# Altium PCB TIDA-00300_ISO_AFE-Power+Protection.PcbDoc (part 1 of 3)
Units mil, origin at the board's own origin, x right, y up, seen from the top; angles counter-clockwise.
Board outline 3622.05 x 2204.8 mil, 4 copper layers (Top Layer, GND Layer, PWR Layer, Bottom Layer), stack 63.6 mil thick; 240 components, 107 nets, 584 pads, 225 vias.
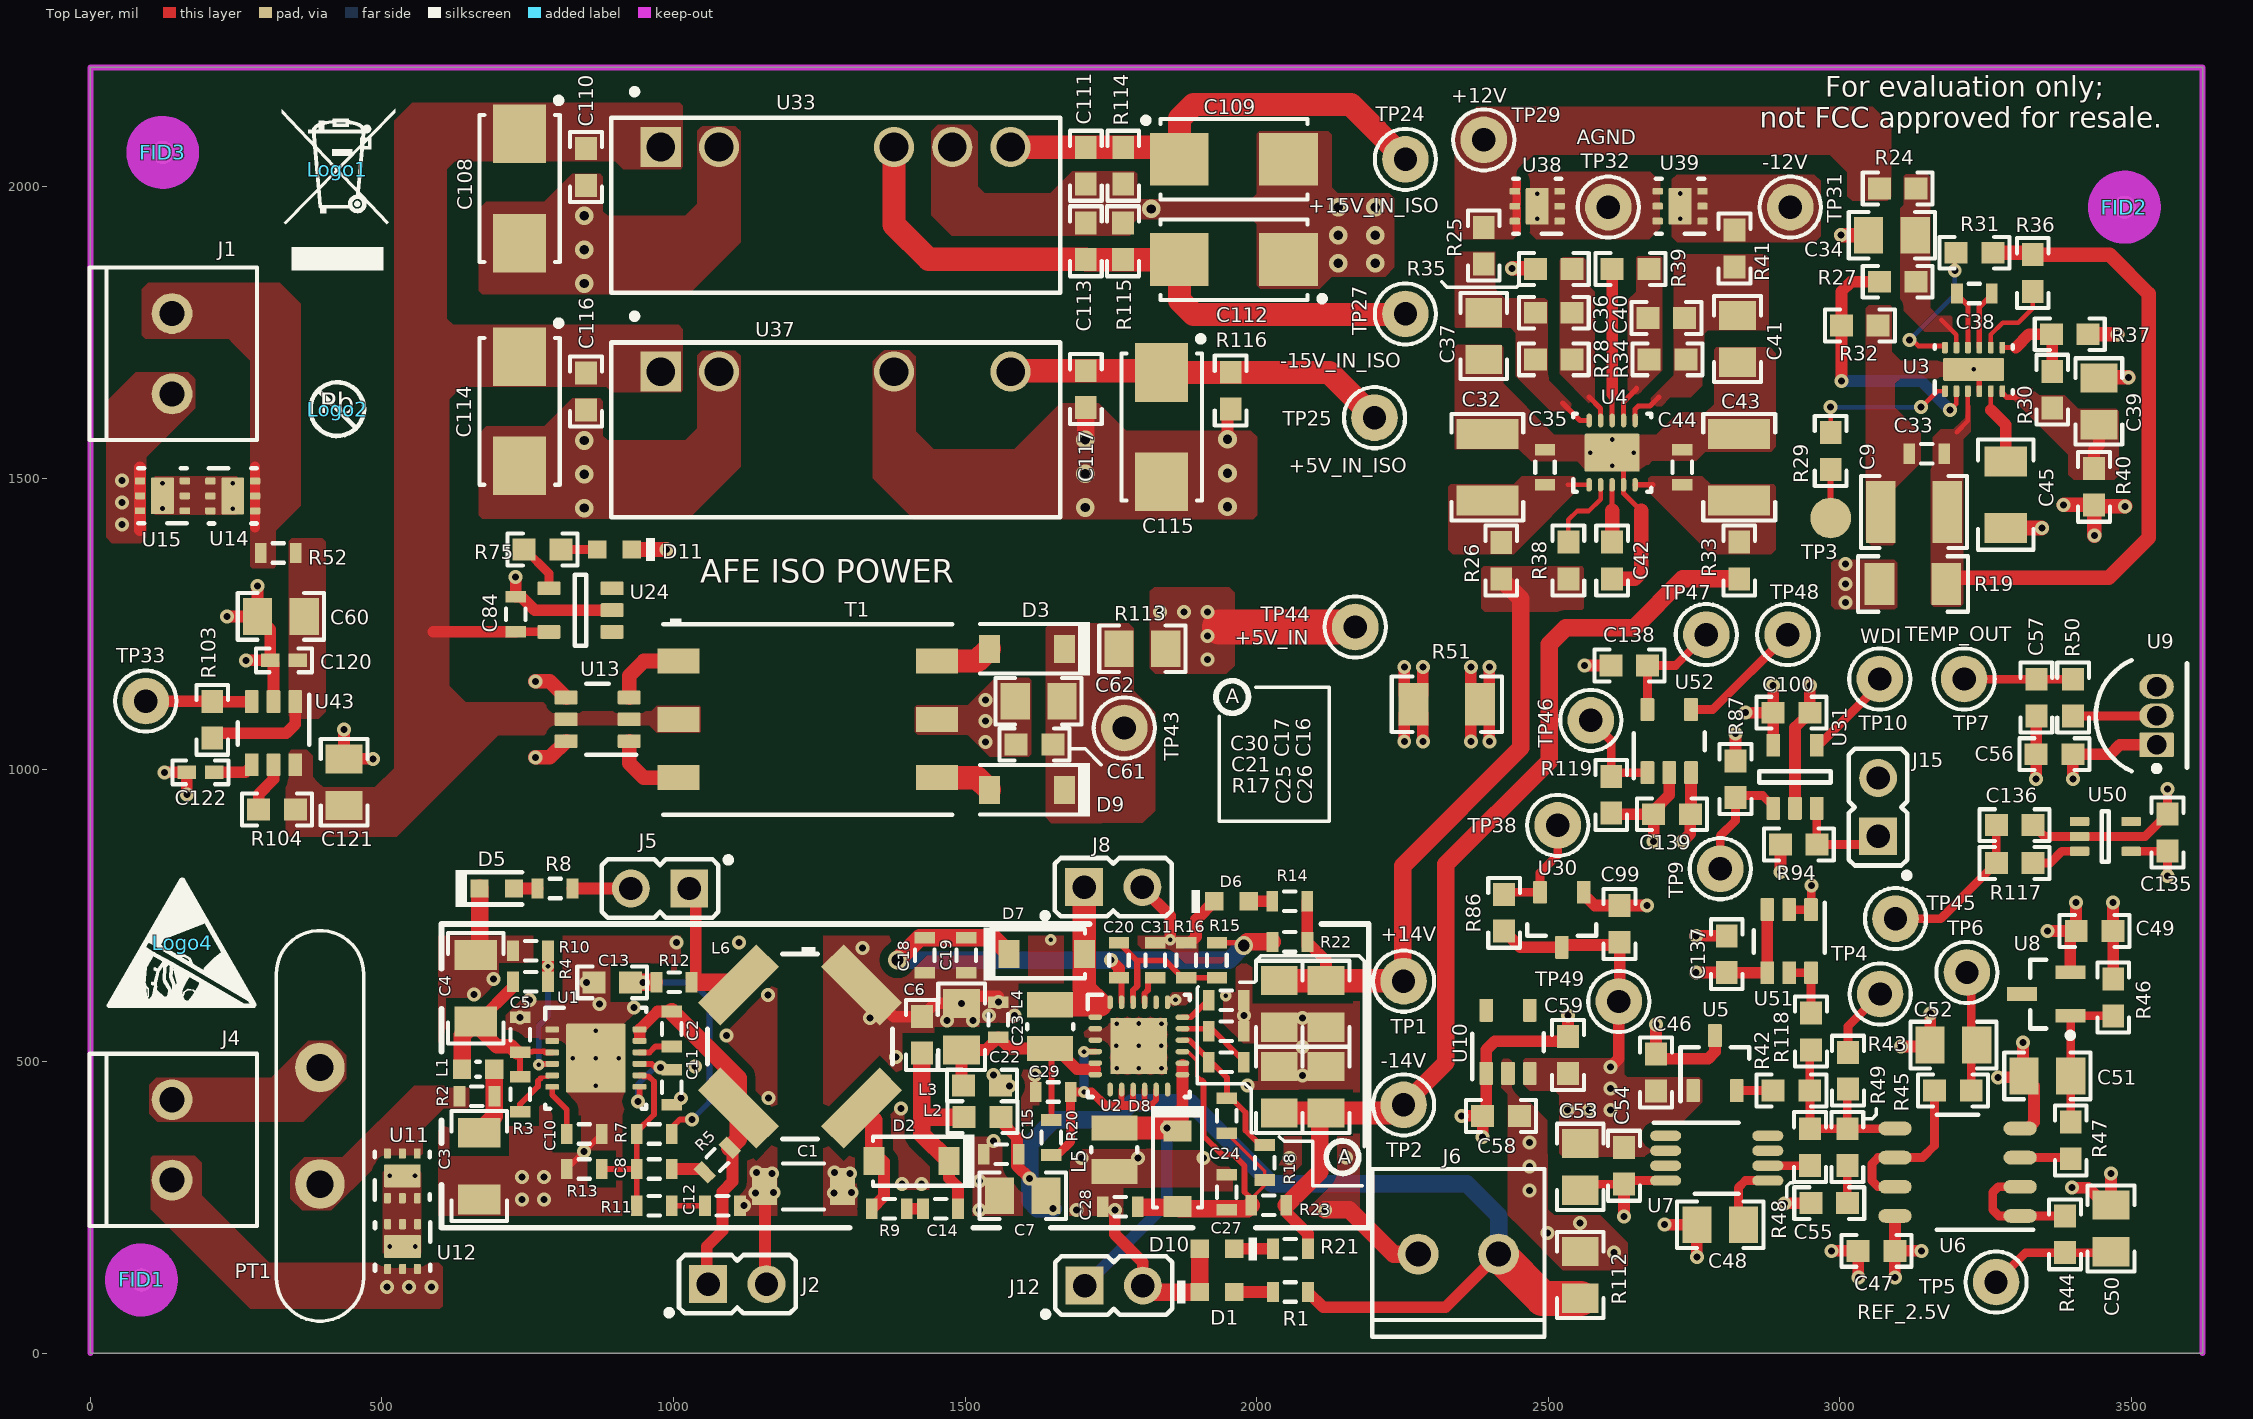
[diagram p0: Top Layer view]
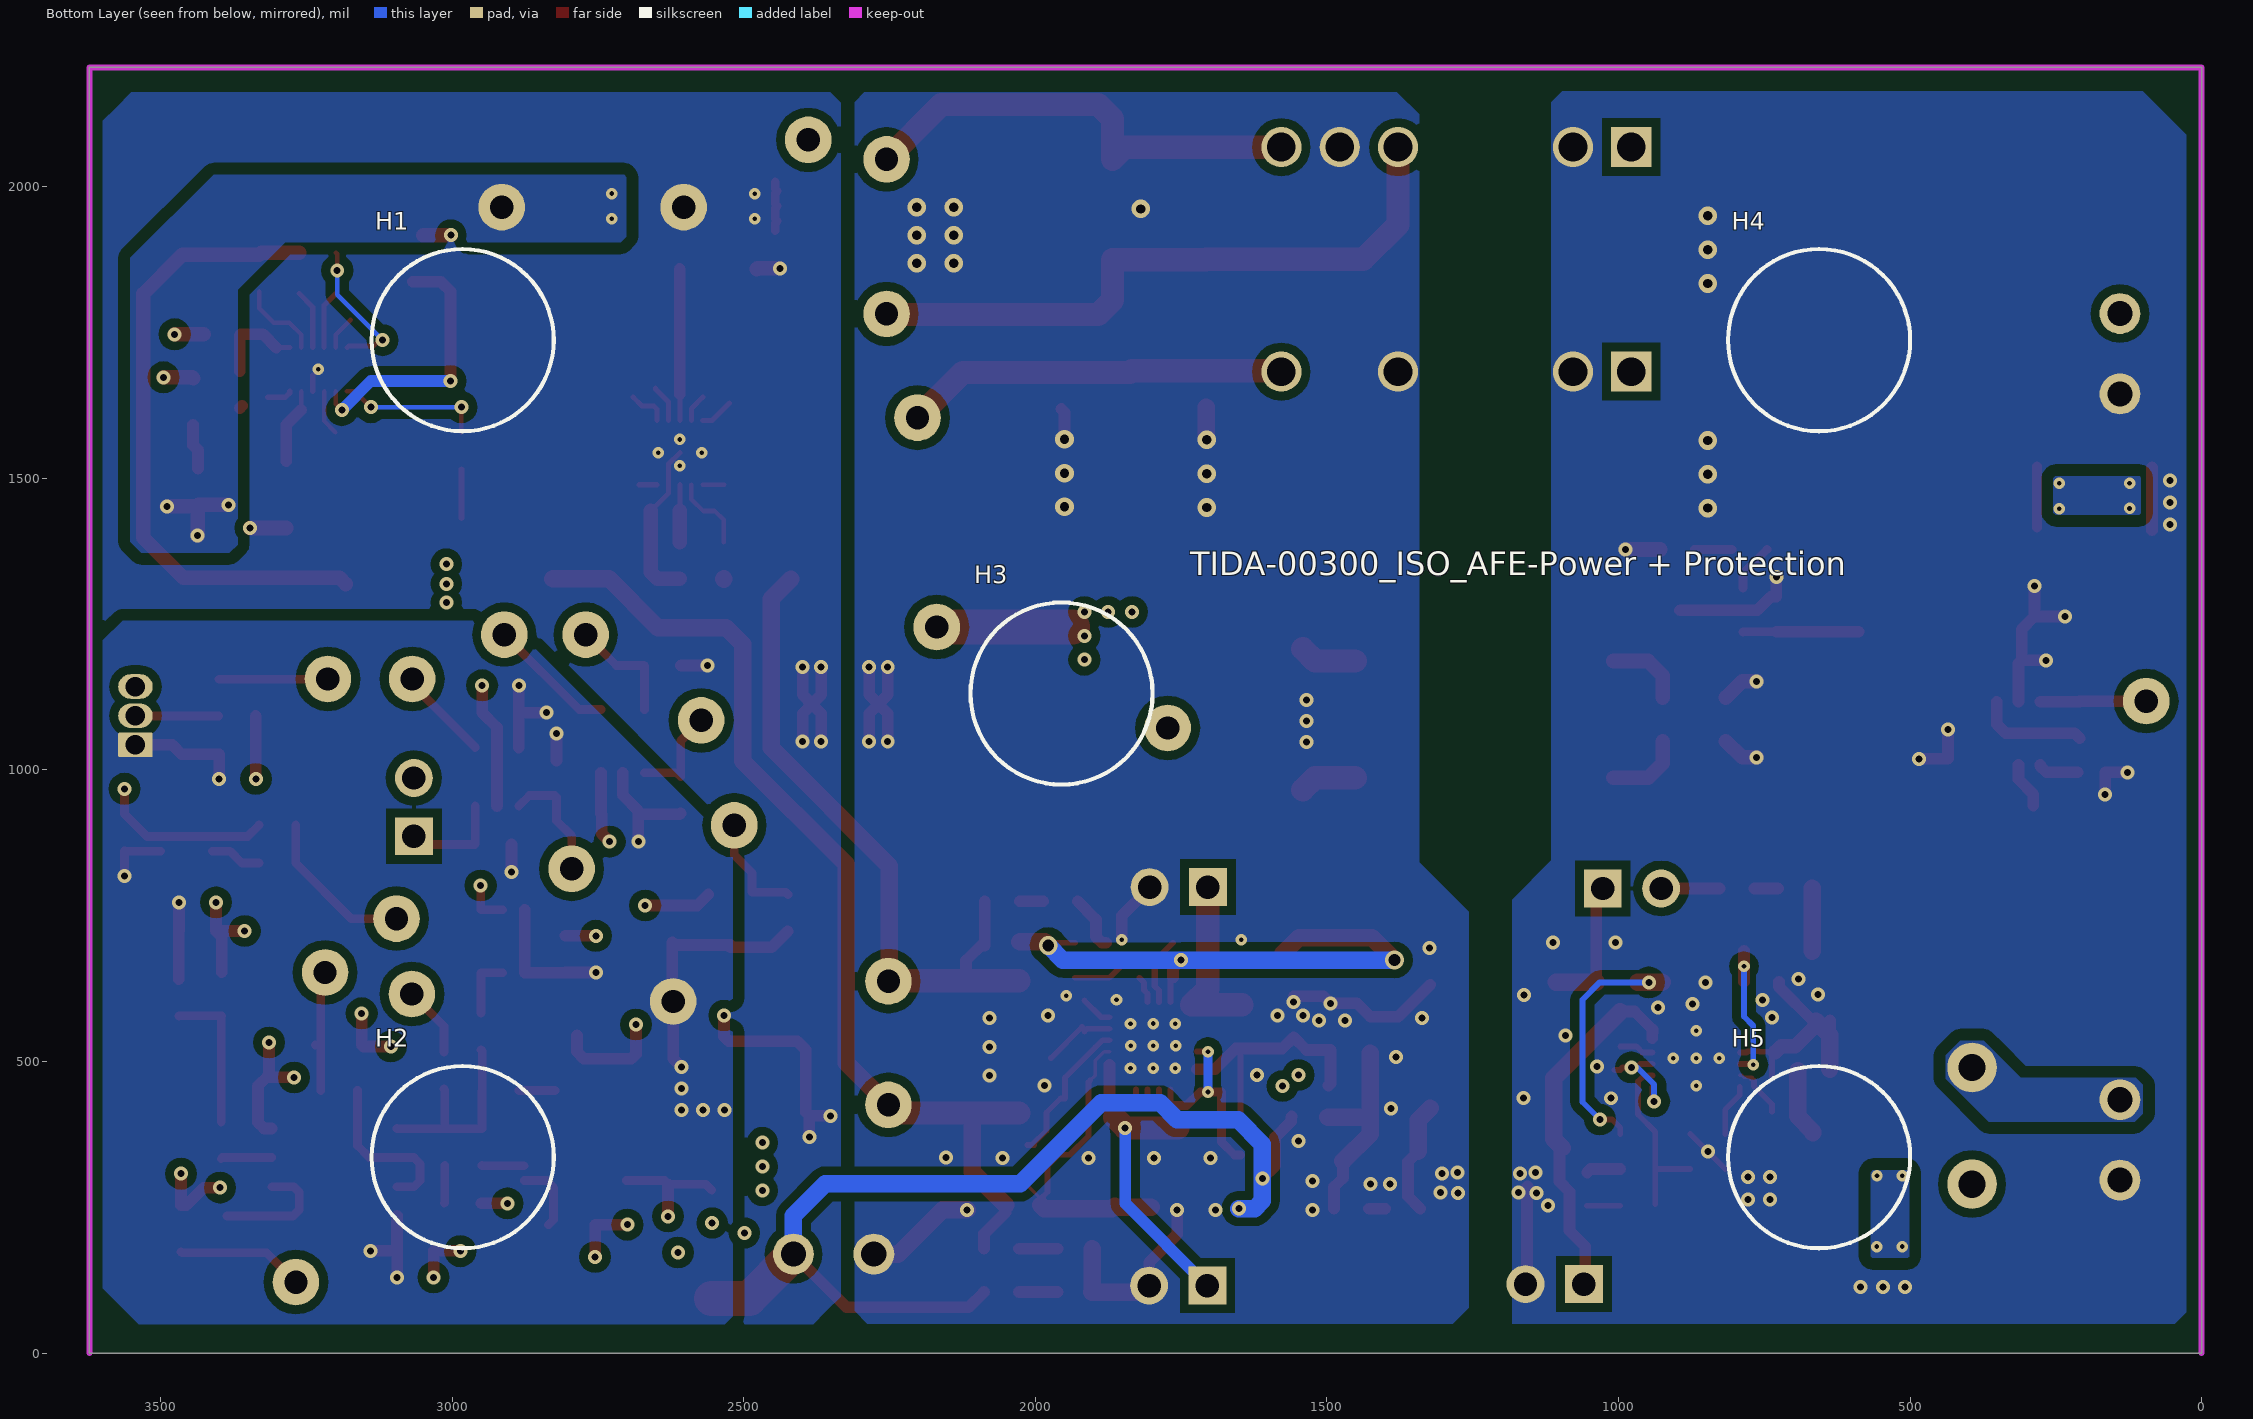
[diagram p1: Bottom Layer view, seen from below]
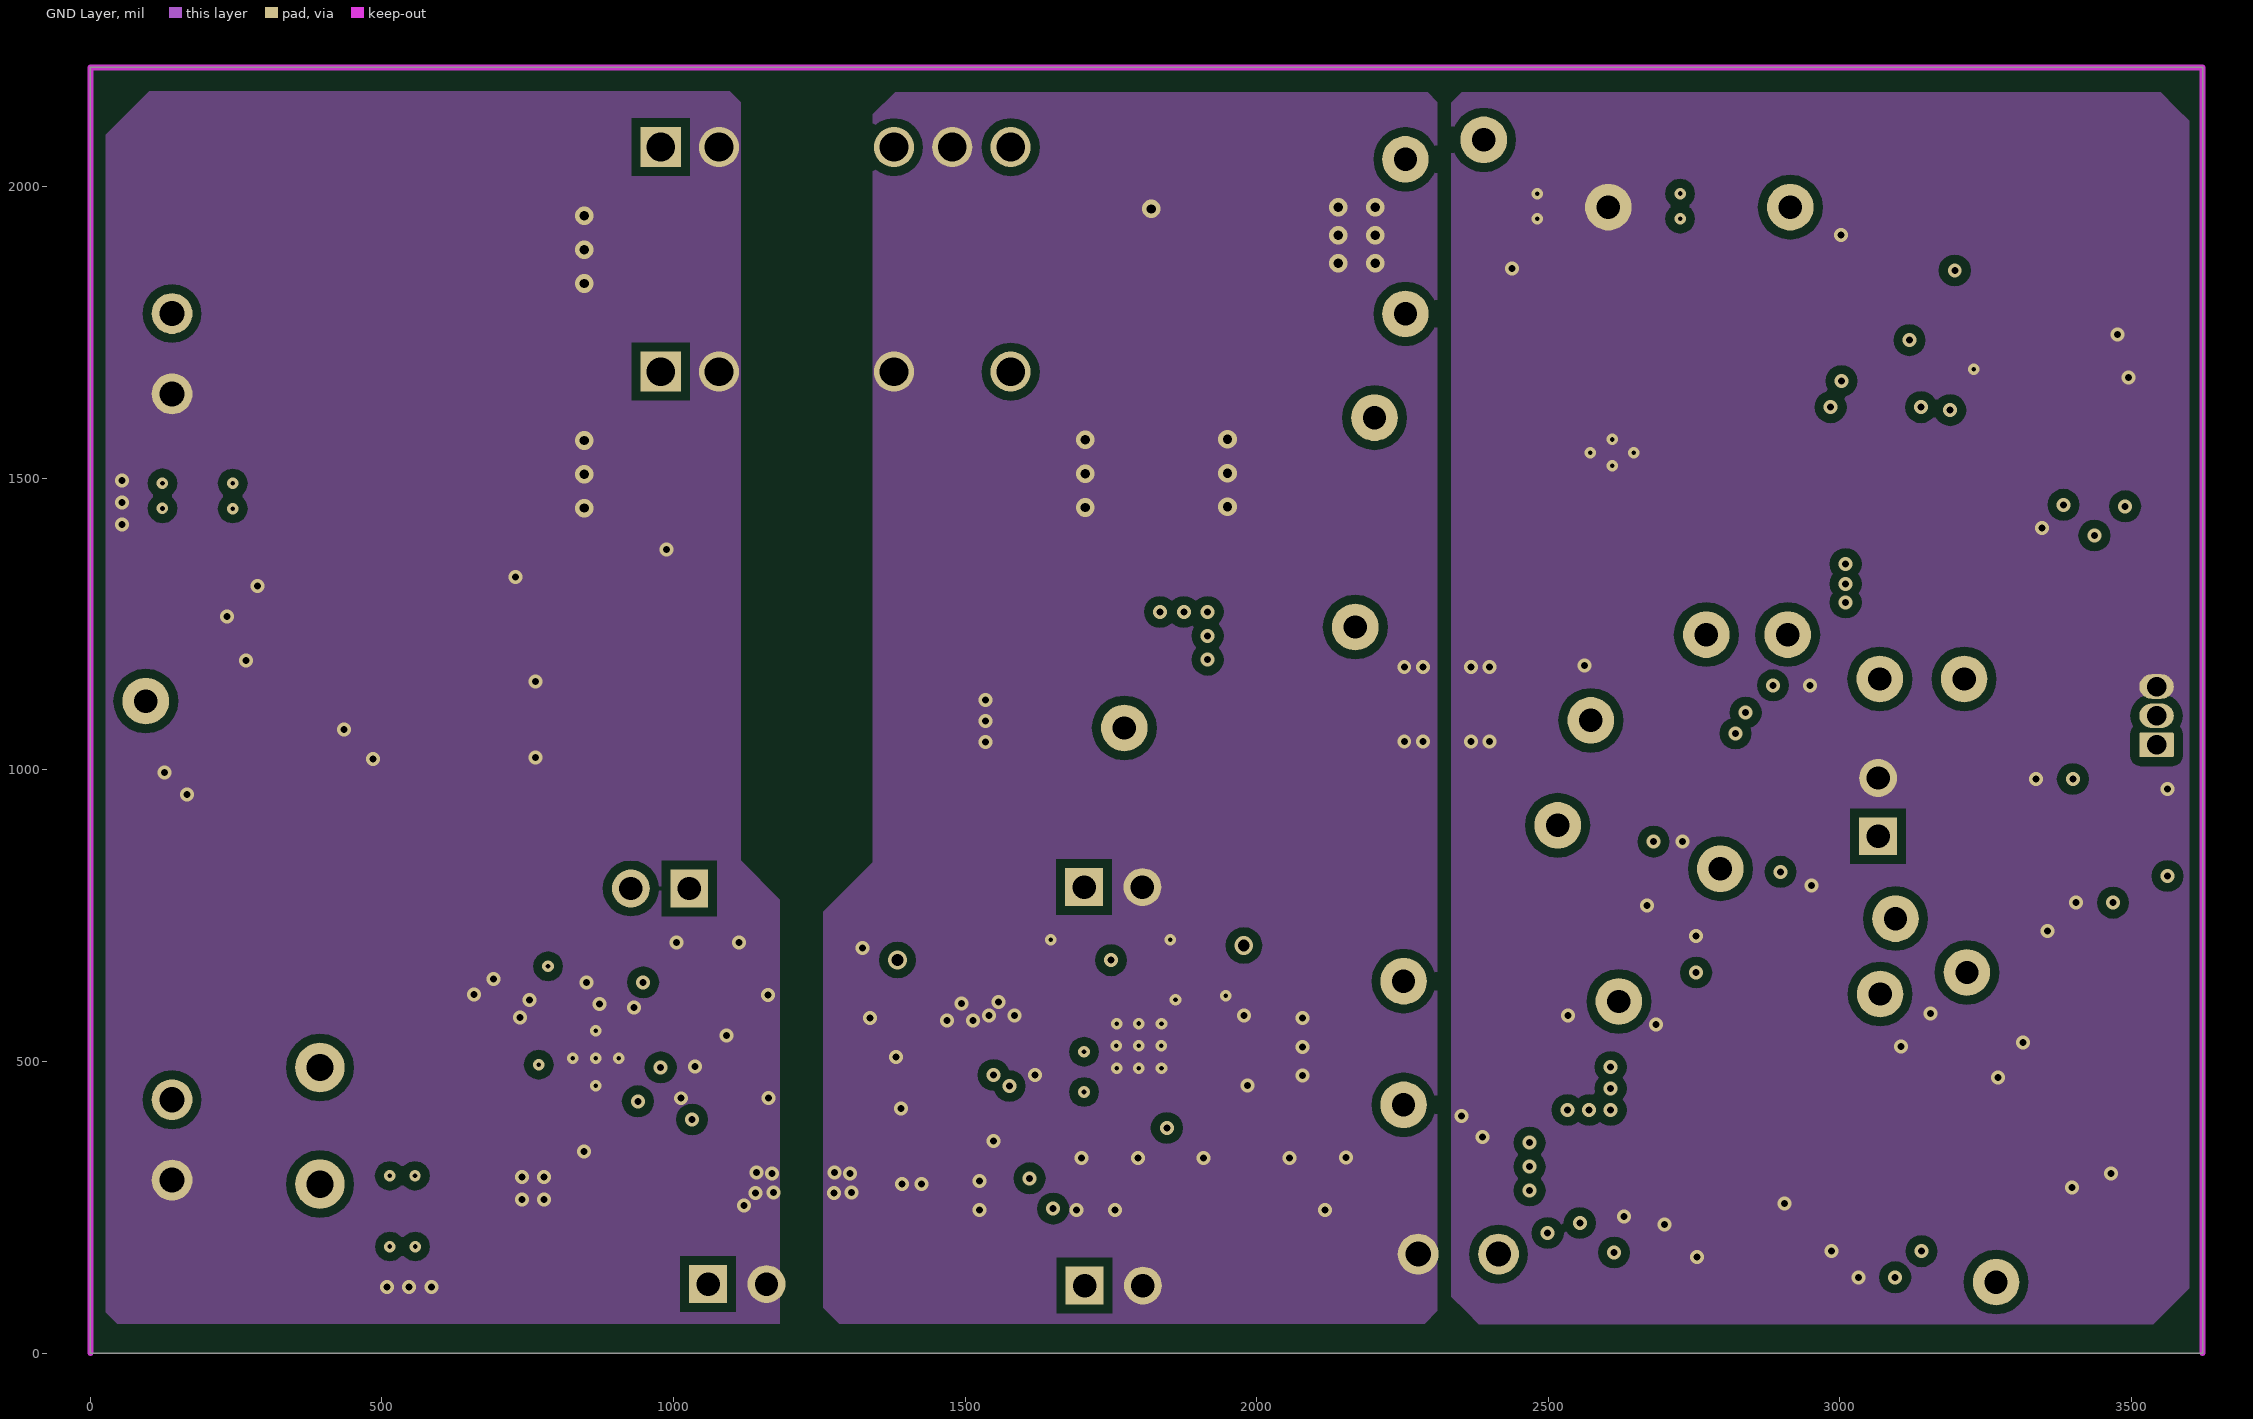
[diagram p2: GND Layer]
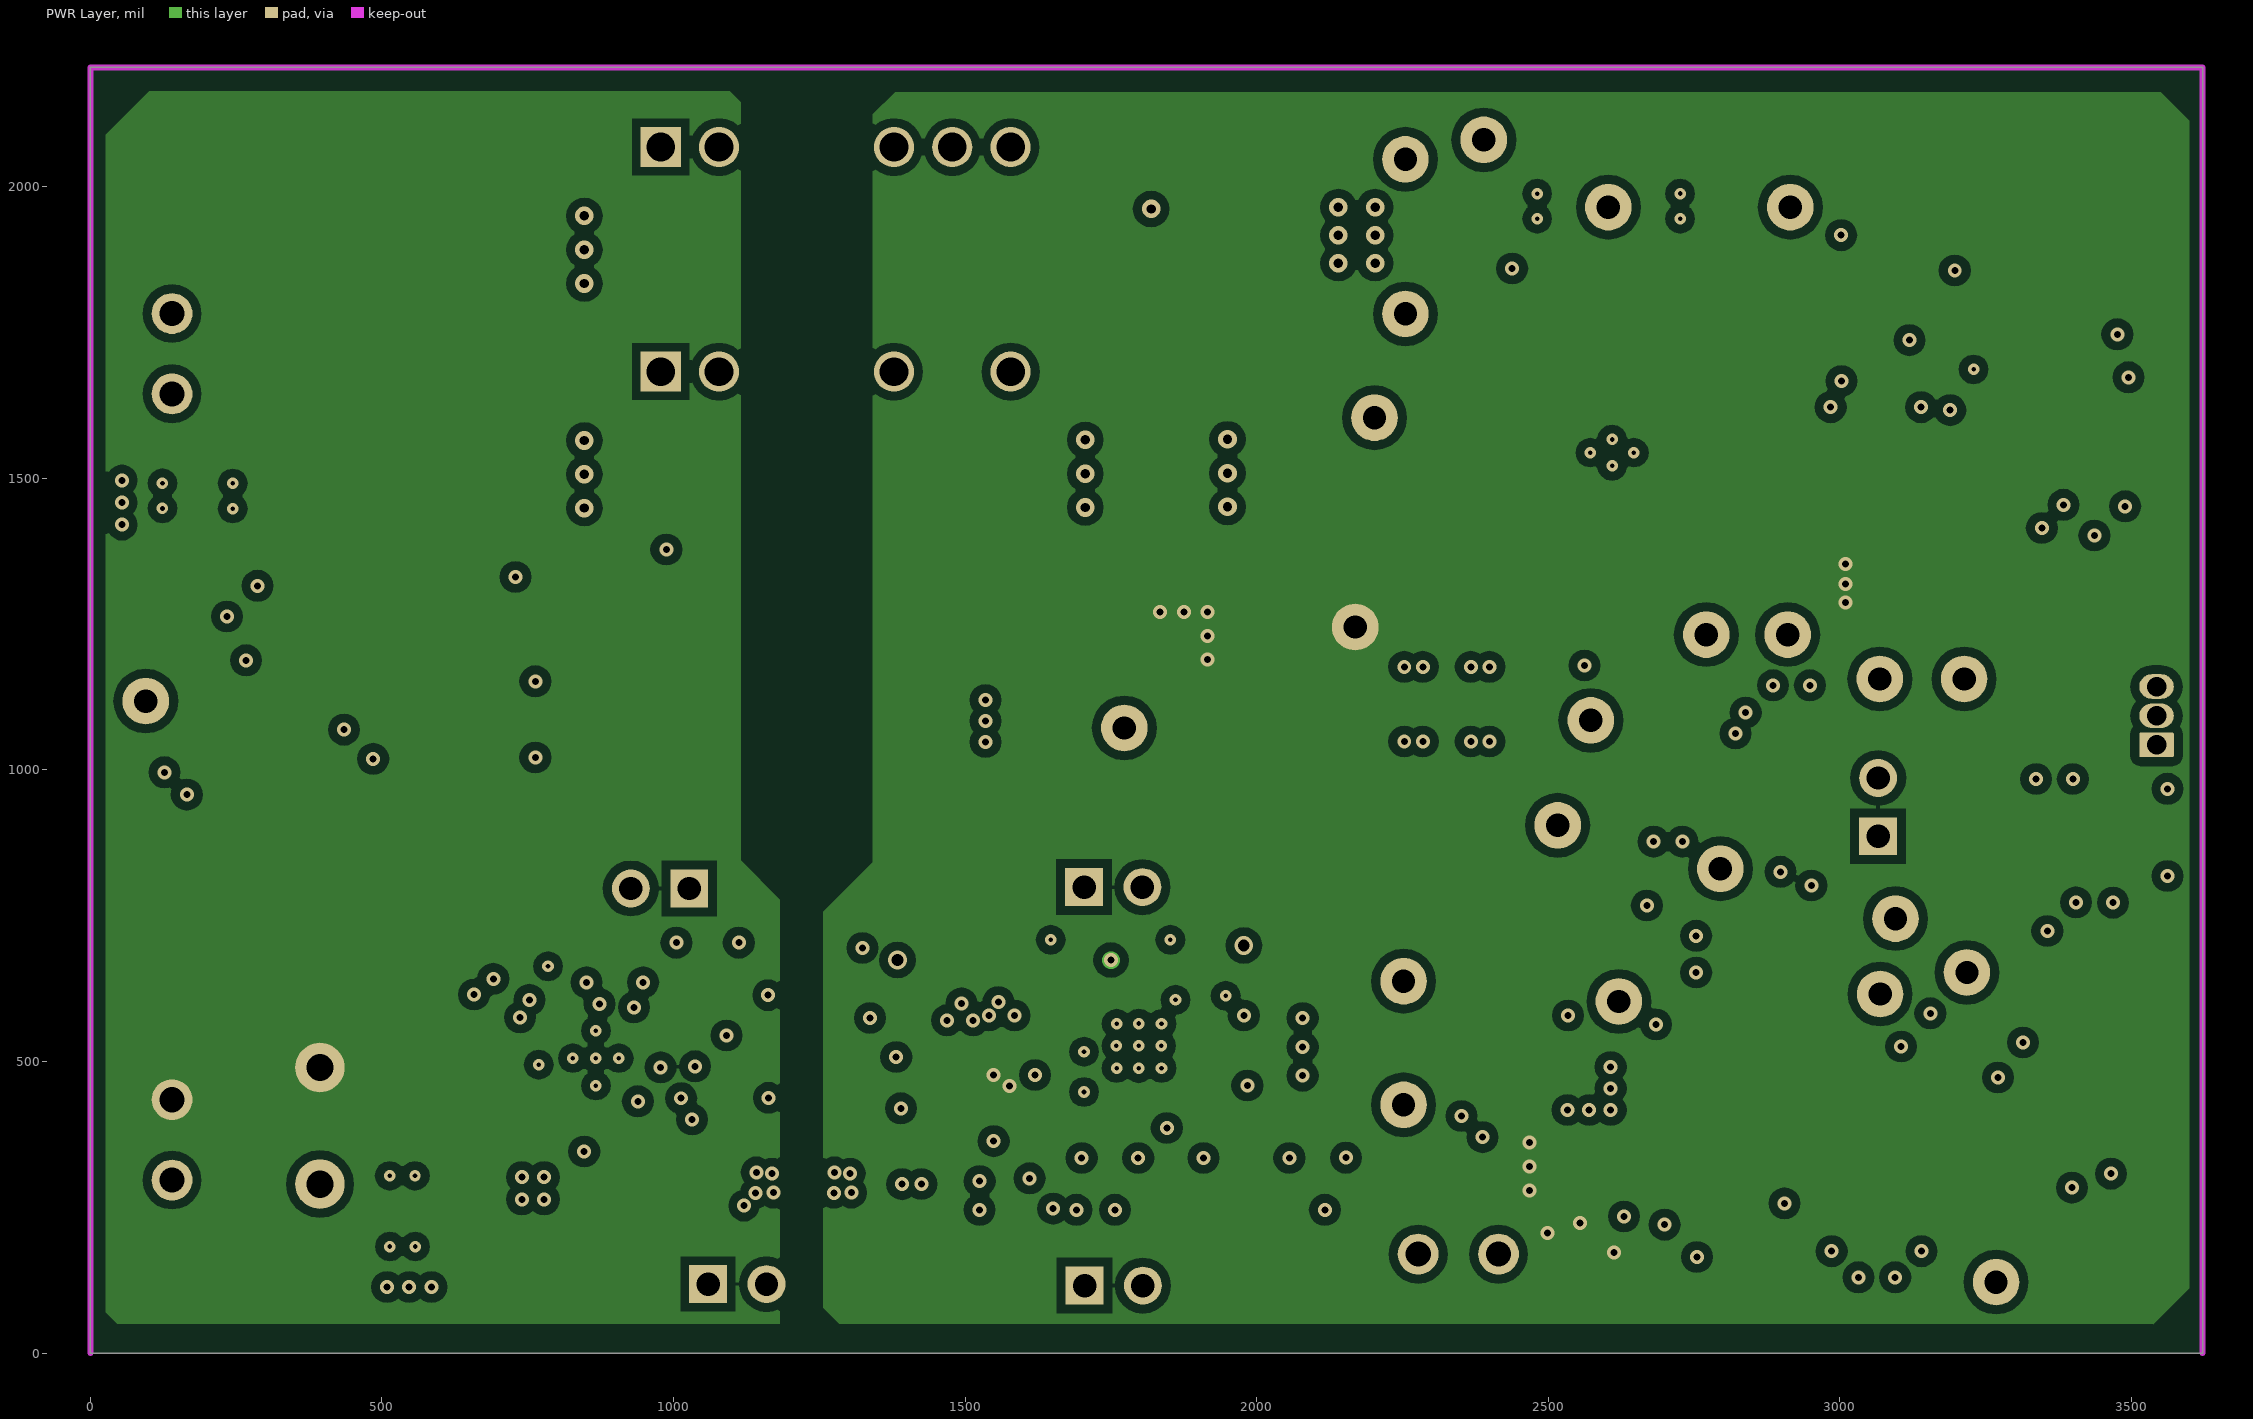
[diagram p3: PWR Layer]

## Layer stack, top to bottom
Top Solder: solder mask 0.3, Solder Resist, Dk 3.5
Top Layer: signal copper 1.4
Dielectric1: core 15, FR-4 High Tg, Dk 4.5
GND Layer: signal copper 1.4
Dielectric 2: prepreg 28, FR-4 High Tg, Dk 4.5
PWR Layer: signal copper 1.4
Dielectric 3: core 15, FR-4 High Tg, Dk 4.5
Bottom Layer: signal copper 1.4
Bottom Solder: solder mask 0.3, Solder Resist, Dk 3.5

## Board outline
0,0 0,2204.72 3622.05,2204.65 3622.05,-0.07

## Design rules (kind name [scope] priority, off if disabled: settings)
AcuteAngle [All] p1: minimum=4.50000000000000E+0001 checktracksonly=FALSE
AssemblyTestPointUsage [All] p1: valid=2
BoardOutlineClearance BoardOutlineClearance_MountingHoles [OnCopper and InComponentClass('Mounting Holes')] p1: gap=30 ignorepadtopadclearanceinfootprint=FALSE
BoardOutlineClearance BoardOutlineClearance_Poly [OnCopper and InPoly] p2: gap=25 ignorepadtopadclearanceinfootprint=FALSE
BoardOutlineClearance [OnCopper and Not InComponentClass('Logo') and not InComponentClass('FiducialMark') and not InRegion(1000,500,4000,800)] p3: gap=15 ignorepadtopadclearanceinfootprint=FALSE
Clearance Clearance_Poly_poly [InPoly vs InPoly] p1: gap=20 ignorepadtopadclearanceinfootprint=FALSE except(0: Arc-Hole Track-Hole SMDPad-Hole THPad-Hole Via-Hole Fill-Hole Poly-Hole Region-Hole Text-Hole)
Clearance Clearance_Keepouts [((IsTrack Or IsArc) And Not InPoly) And IsFree and IsKeepOut vs ((IsTrack Or IsArc) And Not InPoly) And IsFree and IsKeepOut] p2: gap=20 ignorepadtopadclearanceinfootprint=FALSE except(0: Arc-Hole Track-Hole SMDPad-Hole THPad-Hole Via-Hole Fill-Hole Poly-Hole Region-Hole Text-Hole)
Clearance Clearance_Poly [InPolygon] p3: gap=15 ignorepadtopadclearanceinfootprint=FALSE except(0: Arc-Hole Track-Hole SMDPad-Hole THPad-Hole Via-Hole Fill-Hole Poly-Hole Region-Hole Text-Hole)
Clearance [All] p4: gap=7.87 ignorepadtopadclearanceinfootprint=FALSE except(0: Arc-SMDPad Arc-THPad Arc-Hole Track-Hole SMDPad-Hole THPad-Hole Via-Hole Fill-Hole Poly-Hole Region-Hole Text-Hole)
ComponentClearance ComponentClearance_MountingHoles_FiducialMarks [InComponentClass('Mounting Holes') vs InComponentClass('FiducialMark')] p1: gap=10 collisioncheckmode=3 verticalgap=10 showdistances=FALSE
ComponentClearance ComponentClearance_Shunt [InComponentClass('Header') vs InComponentClass('Shunt')] p2: gap=0 collisioncheckmode=3 verticalgap=0 showdistances=FALSE
ComponentClearance ComponentClearance_Logo [InComponentClass('Logo')] p3: gap=5 collisioncheckmode=3 verticalgap=5 showdistances=FALSE
ComponentClearance ComponentClearance_ScrewToNut [(HasFootprint('NY PMS 440 0025 PH')) vs (HasFootprint('Keystone_1902C'))] p4: gap=5 collisioncheckmode=3 verticalgap=10 showdistances=FALSE
ComponentClearance ComponentClearance_MountingHoles [InComponentClass('Mounting Holes')] p5: gap=250 collisioncheckmode=3 verticalgap=100000 showdistances=FALSE
ComponentClearance ComponentClearance_SmallPassives [HasFootprint('0201*') or HasFootprint('0402*') or HasFootprint('0508') or HasFootprint('0603*') or HasFootprint('0612') or HasFootprint('0805*') or HasFootprint('0815*') or HasFootprint('0830*') or HasFootprint('1206*') or HasFootprint('1210*') or HasFootprint('1808*') or HasFootprint('1812*') or HasFootprint('1825*') or HasFootprint('2010*') or HasFootprint('2220*') or HasFootprint('2225*') or HasFootprint('2512*') or HasFootprint('2728*') or HasFootprint('3518*') vs HasFootprint('0201*') or HasFootprint('0402*') or HasFootprint('0508') or HasFootprint('0603*') or HasFootprint('0612') or HasFootprint('0805*') or HasFootprint('0815*') or HasFootprint('0830*') or HasFootprint('1206*') or HasFootprint('1210*') or HasFootprint('1808*') or HasFootprint('1812*') or HasFootprint('1825*') or HasFootprint('2010*') or HasFootprint('2220*') or HasFootprint('2225*') or HasFootprint('2512*') or HasFootprint('2728*') or HasFootprint('3518*')] p6: gap=5 collisioncheckmode=3 verticalgap=5 showdistances=FALSE
ComponentClearance ComponentClearance_THtoSMT [IsThruComponent vs IsSMTComponent] p7: gap=5 collisioncheckmode=3 verticalgap=5 showdistances=FALSE
ComponentClearance ComponentClearance_THtoTH [IsThruComponent vs IsThruComponent] p8: gap=0 collisioncheckmode=3 verticalgap=10 showdistances=FALSE
ComponentClearance [All] p9: gap=10 collisioncheckmode=3 verticalgap=10 showdistances=FALSE
DiffPairsRouting [All] p1: maxlimit=100 minlimit=10 mostfreqgap=10 toplayer_minwidth=15 toplayer_maxwidth=15 toplayer_prefwidth=15 midlayer1_minwidth=15 midlayer1_maxwidth=15 midlayer1_prefwidth=15 midlayer2_minwidth=15 midlayer2_maxwidth=15 midlayer2_prefwidth=15 bottomlayer_minwidth=15 bottomlayer_maxwidth=15 bottomlayer_prefwidth=15 maxuncoupledlength=1000
FabricationTestPointUsage TestPointUsage [All] p1: valid=2 allowmultiple=FALSE
FabricationTestpoint Testpoint [All] p1: side=3 testpointundercomponent=TRUE minsize=40 maxsize=100 preferedsize=60 minholesize=0 maxholesize=40 preferedholesize=32 testpointgrid=1 allowsidetop=TRUE allowsidebottom=TRUE usegrid=TRUE gridtolerance=0.01
FanoutControl Fanout_LCC [IsLCC] p1: bgadir=Out bgaviamode=Centered fanoutstyle=Auto fanoutdirection=Alternating viagrid=1 // Fanout_LCC (Default Rule)
FanoutControl Fanout_BGA [IsBGA] p2: bgadir=Out bgaviamode=Centered fanoutstyle=Auto fanoutdirection=Alternating viagrid=1 // Fanout_BGA (Default Rule)
FanoutControl Fanout_Default [All] p4: bgadir=Out bgaviamode=Centered fanoutstyle=Auto fanoutdirection=Alternating viagrid=1 // Fanout_Default (Default Rule)
FanoutControl Fanout_Small [(CompPinCount < 5)] p5: bgadir=Out bgaviamode=Centered fanoutstyle=Auto fanoutdirection=OutThenIn viagrid=1 // Fanout_Small (Default Rule)
HoleSize [All] p1: absolutevalues=TRUE maxlimit=251 minlimit=7.87 maxpercent=80.000 minpercent=20.000
MinimumAnnularRing MinimumAnnularRing_ThermalPadVias [IsVia and InAnyComponent] p1: minimumring=4
MinimumAnnularRing [All] p2: minimumring=4
MinimumSolderMaskSliver MinimumSolderMaskSliver_Logo [InComponentClass('Logo') vs InComponentClass('Logo')] p1: minsoldermaskwidth=0.7
MinimumSolderMaskSliver [All] p2: minsoldermaskwidth=3.94
PlaneClearance [All] p1: clearance=10
PlaneConnect [All] p1: planeconnectstyle=Relief reliefexpansion=10 reliefentries=4 reliefconductorwidth=10 reliefairgap=10
PolygonConnect PolygonConnectThermalVia [isvia] p1: connectstyle=Direct reliefconductorwidth=10 reliefentries=4 polygonreliefangle="90 Angle" airgapwidth=10
PolygonConnect PolygonConnectThermalPad [((ObjectKind = 'Pad') And (((Name Like 'U*') or (Name Like 'D*')) and (InComponentClass('TIDA-00183_pg-4_Driver') or InComponentClass('TIDA-00183_pg-5_OP_Connector')))) or ((ObjectKind = 'Pad') And (Name like 'U61*'))] p2: connectstyle=Direct reliefconductorwidth=10 reliefentries=4 polygonreliefangle="90 Angle" airgapwidth=10
PolygonConnect [All] p3: connectstyle=Direct reliefconductorwidth=10 reliefentries=4 polygonreliefangle="90 Angle" airgapwidth=5
RoutingVias ThermalPadVias [IsVia and InAnyComponent] p1: holewidth=7.87 width=19.68 viastyle="Through Hole" minholewidth=7.87 minwidth=19.68 maxholewidth=12.99 maxwidth=23.62
RoutingVias [All] p2: holewidth=16 width=34 viastyle="Through Hole" minholewidth=8 minwidth=20 maxholewidth=40 maxwidth=65
SilkToBoardRegionClearance [Not ((IsComment or IsDesignator) And (Hide <> 'False')) and not InRegion(1000,500,4000,800)] p1:
SilkToSilkClearance SilkToSilkClearance_Pb-FreeLogo [(HasFootprint('Pb-Free_Overlay_Medium') OR HasFootprint('Pb-Free_Overlay_Small')) vs (HasFootprint('Pb-Free_Overlay_Medium') OR HasFootprint('Pb-Free_Overlay_Small'))] p1: silktosilkclearance=0
SilkToSilkClearance [All] p2: silktosilkclearance=4
SilkToSolderMaskClearance SilkToComponentPadClearance [IsPad and InAnycomponent] p1: minsilkscreentomaskgap=5 clearancetoexposedcopper=TRUE
SilkToSolderMaskClearance "Silk to Solder Mask Opening" [All] p2: minsilkscreentomaskgap=4 clearancetoexposedcopper=FALSE
SolderMaskExpansion [All] p1: expansion=1.97
Width [All] p1: maxlimit=100 minlimit=6 preferedwidth=10 checkconnectedcopper=TRUE
14 further rules are at their usual default settings.

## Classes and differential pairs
component class "TIDA-00300_ISO_AFE-Power+Protection _Pg3": C1 C2 C3 C4 C5 C6 C7 C8 C10 C11 C12 C13 C14 C15 C60 C61 C62 C84 C108 C109 C110 C111 C112 C113 C114 C115 C116 C117 C120 C121 C122 D1 D2 D3 D5 D9 D11 J1 J2 J4 J5 J6 L1 L2 L6 PT1 R1 R2 R3 R4 R5 R7 R8 R9 R10 R11 R12 R13 R52 R75 R103 R104 R112 R113 R114 R115 R116 T1 TP24 TP25 TP27 TP33 TP43 TP44 U1 U11 U12 U13 U14 U15 U24 U33 U37 U43
component class "TIDA-00300_ISO_AFE-Power+Protection _Pg5": C9 C32 C33 C34 C35 C36 C37 C38 C39 C40 C41 C42 C43 C44 C45 C46 C47 C48 C49 C50 C51 C52 C53 C54 C55 C56 C57 C58 C59 C99 C100 C135 C136 C137 C138 C139 J15 R19 R24 R25 R26 R27 R28 R29 R30 R31 R32 R33 R34 R35 R36 R37 R38 R39 R40 R41 R42 R43 R44 R45 R46 R47 R48 R49 R50 R51 R86 R87 R94 R117 R118 R119 TP3 TP4 TP5 TP6 TP7 TP9 TP10 TP29 TP31 TP32 TP38 TP45 TP46 TP47 TP48 TP49 U3 U4 U5 U6 U7 U8 U9 U10 U30 U31 U38 U39 U50 U51 U52
component class Header: J2 J5 J8 J12 J15
component class AssemblyNote: ZZ1 ZZ2 ZZ3 ZZ4
component class FiducialMark: FID1 FID2 FID3
component class "TIDA-00300_ISO_AFE-Power+Protection _EVM_Hardware_Pg6": FID1 FID2 FID3 H1 H2 H3 H4 H5 Logo1 Logo2 Logo3 Logo4 ZZ1 ZZ2 ZZ3 ZZ4
component class "TIDA-00300_ISO_AFE-Power+Protection _Pg4": C16 C17 C18 C19 C20 C21 C22 C23 C24 C25 C26 C27 C28 C29 C30 C31 D6 D7 D8 D10 J8 J12 L3 L4 L5 R14 R15 R16 R17 R18 R20 R21 R22 R23 TP1 TP2 U2

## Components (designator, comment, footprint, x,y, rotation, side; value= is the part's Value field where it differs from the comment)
C1 "1206GC102KAZ1A" 1206_190 1222.85,285.72 r180 top value=1000pF
C2 "CGA3E2X7R1H103K080AA" 0603S 996.85,555.72 r90 top value=0.01uF
C3 "UMK316B7225KL-T" 1206 666.85,320.72 r270 top value=2.2uF
C4 "UMK316B7225KL-T" 1206 660.85,625.72 r90 top value=2.2uF
C5 "C0603X124K5RAC7867" 0603S 736.85,545.72 r90 top value=0.1uF
C6 "885012206048" 0603 1425.85,545.72 r90 top value=0.22uF
C7 "GRM21BC71E106KE11L" 0805_HV 1598.85,269.72 r180 top value=10uF
C8 "C0603X124K5RAC7867" 0603S 966.85,315.72 r180 top value=0.1uF
C9 "" 1210 3127.11,1441.98 r0 top value=10uF
C10 "885012206034" 0603S 846.85,375.72 r0 top value=1000pF
C11 "CGA3E1X7R1E105K080AC" 0603S 996.85,455.72 r270 top value=1uF
C12 "C1608X7R1H223K080AA" 0603S 1084,252.99 r0 top value=0.022uF
C13 "C1608X7R1A225K080AC" 0603 894.85,635.72 r180 top value=2.2uF
C14 "GCM1885C1H101JA16D" 0603S 1457.85,247.72 r0 top value=100pF
C15 "C0603X124K5RAC7867" 0603S 1562,340.99 r180 top value=0.1uF
C16 "GRM21BC71E106KE11L" 0805_HV 2118.85,598.72 r270 top value=10uF
C17 "GRM21BC71E106KE11L" 0805_HV 2038.85,598.72 r270 top value=10uF
C18 "CGA3E1X7R1E105K080AC" 0603S 1430.85,681.99 r270 top value=1uF
C19 "C0603X124K5RAC7867" 0603S 1502,681.99 r270 top value=0.1uF
C20 "06035A6R8CAT2A" 0603S 1763.85,673.72 r90 top value=6.8pF
C21 "GRM188R71C224KA01D" 0603S 1947.85,551.72 r0 top value=0.22uF
C22 "GRM21BC71E106KE11L" 0805_HV 1493.85,559.72 r90 top value=10uF
C23 "C0603X124K5RAC7867" 0603S 1556.85,571.72 r90 top value=0.1uF
C24 "GRM1885C1H5R6DA01D" 0603S 1948.85,406.72 r270 top value=5.6pF
C25 "GRM21BC71E106KE11L" 0805_HV 2038.85,451.72 r270 top value=10uF
C26 "GRM21BC71E106KE11L" 0805_HV 2118.85,451.72 r270 top value=10uF
C27 "CGA3E1X7R1E105K080AC" 0603S 1948.85,275.72 r270 top value=1uF
C28 "C0603X124K5RAC7867" 0603S 1765.85,250.72 r0 top value=0.1uF
C29 "C0603X124K5RAC7867" 0603S 1650.85,447.72 r180 top value=0.1uF
C30 "885012206087" 0603S 1947.85,604.72 r0 top value=4700pF
C31 "885012206040" 0603S 1825.85,673.72 r90 top value=0.01uF
C32 "" 1210 2395.4,1518.91 r270 top value=10uF
C33 "CGA3E1X7R1E105K080AC" 0603S 3149.2,1541.98 r180 top value=1uF
C34 "C0805C225K8RACTU" 0805_HV 3089.2,1916.98 r180 top value=2.2uF
C35 "CGA3E1X7R1E105K080AC" 0603S 2494.4,1518.99 r90 top value=1uF
C36 "885012206040" 0603 2509.4,1783.93 r0 top value=0.01uF
C37 "C0805C225K8RACTU" 0805_HV 2389.4,1743.99 r270 top value=2.2uF
C38 "CGA3E1X7R1E105K080AC" 0603S 3230.7,1816.98 r180 top value=1uF
C39 "C0805C225K8RACTU" 0805_HV 3444.2,1631.98 r90 top value=2.2uF
C40 "885012206040" 0603 2702.4,1774.99 r180 top value=0.01uF
C41 "C0805C225K8RACTU" 0805_HV 2824.4,1738.99 r270 top value=2.2uF
C42 "885012206040" 0603 2609.4,1358.99 r270 top value=0.01uF
C43 "" 1210 2827.4,1518.91 r270 top value=10uF
C44 "CGA3E1X7R1E105K080AC" 0603S 2729.4,1518.99 r90 top value=1uF
C45 "C3216X7R1E475M160AC" 1206 3284.2,1471.98 r270 top value=4.7uF
C46 "06033D104KAT2A" 0603 2684.81,481.23 r90 top value=0.1uF
C47 "06033D104KAT2A" 0603 3062.81,175.23 r0 top value=0.1uF
C48 "CL21B105KPFNNNE" 0805_HV 2794.81,220.23 r180 top value=1uF
C49 "06033D104KAT2A" 0603 3436.85,723.72 r0 top value=0.1uF
C50 "C2012X7R1H105K125AE" 0805_HV 3464.85,213.72 r90 top value=1uF
C51 "C2012X7R1H105K125AE" 0805_HV 3355.81,475.23 r180 top value=1uF
C52 "C2012X7R1H105K125AE" 0805_HV 3194.81,528.23 r180 top value=1uF
C53 "CL21B105KPFNNNE" 0805_HV 2554.81,319.23 r270 top value=1uF
C54 "06033D104KAT2A" 0603 2629.81,321.23 r270 top value=0.1uF
C55 "EMK107BBJ106MA-T" 0603 2981.81,257.23 r180 top value=10uF
C56 "06033D104KAT2A" 0603 3368,1026.99 r0 top value=0.1uF
C57 "06033D104KAT2A" 0603 3337,1123.99 r90 top value=0.1uF
C58 "06033D104KAT2A" 0603 2418.87,406.69 r180 top value=0.1uF
C59 "CGB3B3X7R0J105K055AB" 0603 2533.87,511.2 r90 top value=1uF
C60 "C2012X5R1E106K085AC" 0805_HV 326.72,1263.14 r180 top value=10uF
C61 "06033D104KAT2A" 0603 1618.85,1043.72 r180 top value=0.1uF
C62 "C2012X5R1E106K085AC" 0805_HV 1625.85,1117.72 r0 top value=10uF
C84 "C0603X124K5RAC7867" 0603S 729.42,1266.99 r90 top value=0.1uF
C99 "06033D104KAT2A" 0603 2622.25,735.99 r90 top value=0.1uF
C100 "06033D104KAT2A" 0603 2917,1098.19 r0 top value=0.1uF
C108 "593D106X9025C2TE3" 6032-28 736,1996.99 r270 top value=10uF
C109 "593D106X9025C2TE3" 6032-28 1961,2046.99 r0 top value=10uF
C110 "06033D104KAT2A" 0603 850,2033.99 r270 top value=0.1uF
C111 "06033D104KAT2A" 0603 1707,2035.99 r270 top value=0.1uF
C112 "593D106X9025C2TE3" 6032-28 1961,1874.99 r180 top value=10uF
C113 "06033D104KAT2A" 0603 1707,1906.58 r270 top value=0.1uF
C114 "593D106X9025C2TE3" 6032-28 736,1614.99 r270 top value=10uF
C115 "593D106X9025C2TE3" 6032-28 1837,1587.99 r270 top value=10uF
C116 "06033D104KAT2A" 0603 850,1648.99 r270 top value=0.1uF
C117 "06033D104KAT2A" 0603 1707,1652.99 r270 top value=0.1uF
C120 "CGA2B2C0G1H102J050BA" 0402 332,1187.99 r180 top value=1000pF
C121 "C2012X5R1E106K085AC" 0805_HV 435,978.99 r90 top value=10uF
C122 "CGA2B2C0G1H102J050BA" 0402 189,995.99 r180 top value=1000pF
C135 "06033D104KAT2A" 0603 3561.61,892.58 r270 top value=0.1uF
C136 "06033D104KAT2A" 0603 3299.75,905.38 r180 top value=0.1uF
C137 "06033D104KAT2A" 0603 2806,683.99 r90 top value=0.1uF
C138 "06033D104KAT2A" 0603 2639,1178.99 r0 top value=0.1uF
C139 "06033D104KAT2A" 0603 2712.06,924.02 r0 top value=0.1uF
D1 "LTST-C190KGKT" LED_LTST-C190_G 1931.85,104.72 r180 top value=Green
D2 "NTS245SFT1G" SOD-123FL 1408,328.99 r180 top value=45V
D3 "1N5819HW-7-F" SOD-123 1605.85,1207.72 r180 top value=40V
D5 "LTST-C190CKT" LED_LTST-C190_Red 696.85,796.72 r180 top value=Red
D6 "LTST-C190KGKT" LED_LTST-C190_G 1956.85,774.72 r180 top value=Green
D7 "NTS245SFT1G" SOD-123FL 1639.85,684.72 r0 top value=45V
D8 "NTS245SFT1G" SOD-123FL 1864,315.99 r270 top value=45V
D9 "1N5819HW-7-F" SOD-123 1605.85,965.72 r180 top value=40V
D10 "LTST-C190KGKT" LED_LTST-C190_G 1931.85,178.72 r0 top value=Green
D11 "LTST-C190KGKT" LED_LTST-C190_G 899,1377.99 r0 top value=Green
FID1 "Fiducial" Fiducial10-30 87.68,125.41 r0 top
FID2 "Fiducial" Fiducial10-30 3488,1964.99 r0 top
FID3 "Fiducial" Fiducial10-30 124,2058.99 r0 top
H1 "SJ61A1" Bumpon_SJ61A1 2982,1736.99 r180 bottom
H2 "SJ61A1" Bumpon_SJ61A1 2982,335.99 r180 bottom
H3 "SJ61A1" Bumpon_SJ61A1 1955,1130.99 r180 bottom
H4 "SJ61A1" Bumpon_SJ61A1 656,1736.99 r180 bottom
H5 "SJ61A1" Bumpon_SJ61A1 656,335.99 r180 bottom
J1 "1751248" CONN_1751248 140,1713.72 r270 top
J2 "PBC02SAAN" Sullins_PBC02SAAN 1109.37,118.24 r90 top
J4 "1751248" CONN_1751248 140,365.62 r270 top
J5 "PBC02SAAN" Sullins_PBC02SAAN 976.85,796.72 r270 top
J6 "1751248" CONN_1751248 2345.75,169.72 r0 top
J8 "PBC02SAAN" Sullins_PBC02SAAN 1754,798.99 r90 top
J12 "PBC02SAAN" Sullins_PBC02SAAN 1754.85,115.72 r90 top
J15 "PBC02SAAN" Sullins_PBC02SAAN 3065.54,936.17 r180 top
L1 "2.2uH" 0603L 664.85,486.72 r180 top
L2 "2.2uH" 0603 1529.85,404.72 r0 top
L3 "BLM18KG601SN1D" 0603 1528.85,458.72 r180 top value="600 ohm"
L4 "74404024100" WE_LQS_252012 1645.85,559.72 r90 top value=10uH
L5 "74404024100" WE_LQS_252012 1755.85,348.72 r270 top value=10uH
L6 "74489430220" WE-TDC_8018 1216.85,525.72 r315 top value=22uH
Logo1 "WEEE logo" WEEE_Minimum 423.64,2028.96 r0 top
Logo2 "Pb-Free Symbol" Pb-Free_Overlay_Small 423.18,1618.61 r0 top
Logo3 "FCC disclaimer" FCC_disclaimer_stacked 1542.39,-2876.59 r0 top
Logo4 "ESD Susceptible" ESD_Overlay_Medium 157.25,702.99 r0 top
PT1 "B59830C0160A070" POLYSWITCH_RXE135 393.7,389.72 r270 top
R1 "CRCW06031K21FKEA" 0603S 2057.85,104.72 r180 top value=1.21k
R2 "CRCW06031R00FKEA" 0603S 662.85,440.72 r180 top value=1.00
R3 "CRCW0603113KFKEA" 0603S 736.85,443.72 r270 top value=113k
R4 "CRCW060316K9FKEA" 0603S 754.85,636.72 r180 top value=16.9k
R5 "CRCW060327K4FKEA" 0603S 1075,330.99 r225 top value=27.4k
R7 "CRCW06033K48FKEA" 0603S 966.85,375.72 r0 top value=3.48k
R8 "CRCW06035K36FKEA" 0603S 796.85,796.72 r0 top value=5.36k
R9 "CRCW0603150RFKEA" 0603S 1369.85,247.72 r180 top value=150
R10 "CRCW06032K00FKEA" 0603S 754.85,689.72 r0 top value=2.00k
R11 "CRCW060342R2FKEA" 0603S 966.85,252.72 r180 top value=42.2
R12 "ERJ-3GEY0R00V" 0603S 1000.85,635.72 r0 top value=0
R13 "CRCW06032K00FKEA" 0603S 846.85,315.72 r0 top value=2.00k
R14 "CRCW06035K36FKEA" 0603S 2056.85,774.72 r180 top value=5.36k
R15 "CRCW0603976KFKEA" 0603S 1931.85,673.72 r90 top value=976k
R16 "CRCW060386K6FKEA" 0603S 1878.85,673.72 r270 top value=86.6k
R17 "CRCW0603105KFKEA" 0603S 1947.85,498.72 r0 top value=105k
R18 "CRCW06031M30FKEA" 0603S 2013.85,326.72 r90 top value=1.30Meg
R19 "CRCW12060000Z0EA" 1206 3125.27,1318.82 r180 top value=0
R20 "CRCW0603100RFKEA" 0603S 1647.85,369.72 r90 top value=100
R21 "CRCW06035K36FKEA" 0603S 2057.85,178.72 r0 top value=5.36k
R22 "CRCW06031R00FKEA" 0603S 2057,704.99 r0 top value=1.00
R23 "CRCW06031R00FKEA" 0603S 2020.85,253.72 r0 top value=1.00
R24 "CRCW06030000Z0EA" 0603 3099.2,1996.98 r180 top value=0
R25 "CRCW06030000Z0EA" 0603 2389.4,1898.99 r90 top value=0
R26 "CRCW06030000Z0EA" 0603 2419.4,1358.84 r90 top value=0
R27 "CRCW0603249KFKEA" 0603 3099.2,1836.98 r0 top value=249k
R28 "CRCW0603249KFKEA" 0603 2509.4,1703.99 r180 top value=249k
R29 "CRCW060310K0FKEA" 0603 2984.2,1546.98 r90 top value=10k
R30 "CRCW0603249KFKEA" 0603 3364.2,1651.98 r270 top value=249k
R31 "CRCW06030000Z0EA" 0603 3230.7,1886.98 r180 top value=0
R32 "CRCW060375K0FKEA" 0603 3034.2,1761.98 r180 top value=75.0k
R33 "CRCW06030000Z0EA" 0603 2827.4,1358.99 r90 top value=0
R34 "CRCW0603249KFKEA" 0603 2704.4,1703.93 r0 top value=249k
R35 "RC0603FR-0727KL" 0603 2509.4,1858.99 r0 top value=27.0k
R36 "CRCW06030000Z0EA" 0603 3330.7,1851.98 r270 top value=0
R37 "CRCW060375K0FKEA" 0603 3394.2,1746.98 r180 top value=75.0k
R38 "CRCW06030000Z0EA" 0603 2534.4,1358.99 r90 top value=0
R39 "RC0603FR-0724KL" 0603 2640.9,1858.99 r0 top value=24.0k
R40 "CRCW06030000Z0EA" 0603 3435.7,1485.48 r270 top value=0
R41 "CRCW06030000Z0EA" 0603 2819.4,1893.99 r90 top value=0
R42 "CRCW06030000Z0EA" 0603 2916.81,450.23 r0 top value=0
R43 "CRCW06030000Z0EA" 0603 3013.94,484.19 r270 top value=0
R44 "CRCW0603100RFKEA" 0603 3385.85,203.72 r270 top value=100
R45 "CRCW0603100RFKEA" 0603 3193.81,450.23 r0 top value=100
R46 "CRCW06032K55FKEA" 0603 3468.85,609.72 r270 top value=2.55k
R47 "CRCW0603100RFKEA" 0603 3395.81,364.73 r270 top value=100
R48 "CRCW06030000Z0EA" 0603 2948.81,353.23 r90 top value=0
R49 "CRCW06030000Z0EA" 0603 3012.81,353.23 r270 top value=0
R50 "CRCW0603100RFKEA" 0603 3400,1123.99 r90 top value=100
R51 "RC1206JR-070RL" 1206 2326,1112.72 r180 top value=0
R52 "CRCW06031R00FKEA" 0603S 322,1371.99 r180 top value=1.00
R75 "ERJ-3EKF1001V" 0603 775.42,1377.99 r0 top value=1.00k
R86 "RC0603FR-0710KL" 0603 2424.25,754.99 r90 top value=10.0k
R87 "RC0603FR-0710KL" 0603 2821,984.19 r270 top value=10.0k
R94 "RC0603FR-0710KL" 0603 2929.54,872.17 r0 top value=10.0k
R103 "ERJ-3GEY0R00V" 0603 209,1085.99 r270 top value=0
R104 "ERJ-3GEY0R00V" 0603 320,931.99 r0 top value=0
R112 "ERJ-6GEY0R00V" 0805_HV 2555,133.99 r90 top value=0
R113 "ERJ-6GEY0R00V" 0805_HV 1804,1207.99 r0 top value=0
R114 "RC0603FR-0710KL" 0603 1771,2035.99 r270 top value=10.0k
R115 "RC0603FR-0710KL" 0603 1770.61,1906.58 r270 top value=10.0k
R116 "CRCW06031K00FKEA" 0603 1955.39,1650.41 r90 top value=1.00k
R117 "CRCW0603100RFKEA" 0603 3299.75,840.38 r180 top value=100
R118 "CRCW06030000Z0EA" 0603 2950.31,551.49 r270 top value=0
R119 "RC0603FR-0710KL" 0603 2608.06,957.31 r90 top value=10.0k
T1 "750315371" Wurth_750315371 1230.11,1086.72 r0 top value=105uH
TP1 "5000" Keystone5000 2251.85,637.72 r0 top
TP2 "5000" Keystone5000 2251.85,425.72 r90 top
TP3 "Pogo Pad" PogoPad 2984.2,1431.98 r90 top
TP4 "5002" Keystone5002 3069,615.72 r0 top
TP5 "5000" Keystone5000 3267.85,121.72 r90 top
TP6 "5000" Keystone5000 3217.85,652.72 r180 top
TP7 "5002" Keystone5002 3213,1155.99 r90 top
TP9 "5002" Keystone5002 2795.06,830.59 r180 top
TP10 "5002" Keystone5002 3068.54,1155.99 r270 top
TP24 "5000" Keystone5000 2255,2046.99 r180 top
TP25 "5000" Keystone5000 2202,1603.99 r0 top
TP27 "5000" Keystone5000 2255,1781.99 r180 top
TP29 "5000" Keystone5000 2389.39,2080.41 r90 top
TP31 "5000" Keystone5000 2915,1964.99 r90 top
TP32 "5001" Keystone5001 2603,1964.99 r90 top
TP33 "5002" Keystone5002 95,1117.99 r90 top
TP38 "5002" Keystone5002 2516.2,904.99 r90 top
TP43 "5000" Keystone5000 1773,1071.99 r90 top
TP44 "5000" Keystone5000 2169,1244.99 r90 top
TP45 "5002" Keystone5002 3095.39,744.99 r90 top
TP46 "5002" Keystone5002 2572.96,1084.99 r90 top
TP47 "5002" Keystone5002 2771,1231.99 r90 top
TP48 "5002" Keystone5002 2910.5,1231.99 r90 top
TP49 "5000" Keystone5000 2621,602.99 r90 top
U1 "LM5160DNTR" DNT0012B 866.85,505.72 r0 top
U2 "TPS65130RGER" RGE0024B 1797.85,526.72 r0 top
U3 "LM27762DSST" DSS0012B 3229.36,1686.82 r90 top
U4 "TPS7A3901DSC" DSC0010J 2609.4,1543.99 r90 top
U5 "REF3025AIDBZR" DBZ0003A_N 2785.81,497.23 r90 top
U6 "OPA2376AID" D0008A_N 3201.81,310.23 r180 top
U7 "REF5025AIDGKT" DGK0008A_N 2788.81,334.23 r0 top
U8 "LM4040AIM3-2.5/NOPB" MF03A_N 3353.85,615.72 r180 top
U9 "LMT84LPM" LP0003A_straight 3543,1092.99 r180 top
U10 "TLV70433DBVR" DBV0005A_N 2430.87,533.69 r90 top
U11 "TVS3300DRVR" DRV0006A 535,303.99 r90 top
U12 "TVS0500DRVR" DRV0006A 535.28,182.72 r270 top
U13 "SN6505BDBVR" DBV0006A_N 869.85,1086.72 r180 top
U14 "TVS0500DRVR" DRV0006A 244.15,1469.74 r0 top
U15 "TVS0500DRVR" DRV0006A 123.61,1469.99 r180 top
U24 "TPS2400DBVR" DBV0005A_N 840.42,1273.99 r180 top
U30 "TPS3839E16DBZR" DBZ0003A_N 2523.25,742.99 r270 top
U31 "TPS3828-33DBVR" DBV0005A_N 2923,988.19 r90 top
U33 "DCH010515DN7" EDJ0005A 1278,2067.99 r0 top
U37 "DCH010505SN7" EDJ0004A 1278,1682.99 r0 top
U38 "TVS1400DRVR" DRV0006A 2481,1966.65 r180 top
U39 "TVS1400DRVR" DRV0006A 2726,1966.71 r180 top
U43 "TPS22917DBVR" DBV0006A_N 314,1062.99 r270 top
U50 "TMP235DCK" DCK0005A_N 3455.22,885.99 r0 top
U51 "REF3425IDBVR" DBV0006A_N 2913,706.3 r270 top
U52 "TPS3840DL30DBVR" DBV0005A_N 2707.36,1049.45 r90 top
ZZ1 "This Assembly Note is for PCB labels only" AssemblyNoteLabel -230.15,3445.72 r0 top
ZZ2 "This Assembly Note will show in the PcbDoc and associated outputs" AssemblyNote -230.15,3336.83 r0 top
ZZ3 "This Assembly Note will show in the PcbDoc and associated outputs" AssemblyNote -230.15,3248.28 r0 top
ZZ4 "This Assembly Note will show in the PcbDoc and associated outputs" AssemblyNote -230.15,3159.72 r0 top

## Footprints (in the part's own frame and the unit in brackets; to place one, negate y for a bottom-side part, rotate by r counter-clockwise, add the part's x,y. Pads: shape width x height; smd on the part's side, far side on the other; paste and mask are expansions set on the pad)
0402 [mm] "0402 from SM-752 data"
  rect 0.8x0.6 smd: 1(-0.6,0) 2(0.6,0)
  silkscreen extent -1.22,-0.52 1.22,0.52, body extent -0.55,-0.3 0.55,0.3, height 0.6
0603 [mm] "0603 from SM-752 data"
  rect 1x0.95 smd: 1(-0.8,0) 2(0.8,0)
  silkscreen extent -1.52,-0.69 1.52,0.69, body extent -0.87,-0.47 0.87,0.47, height 1
0603L [mm] "0603 from SM-752 data"
  rect 0.8x0.85 smd: 1(-0.7,0) 2(0.7,0)
  silkscreen extent -0.07,-0.32 0.07,0.32, body extent -0.87,-0.47 0.87,0.47, height 1
0603S [mil]
  rect 20x35 smd: 1(-30,0) 2(30,0)
  silkscreen extent -10,-17 10,17, body extent -34,-19 34,19, height 39
0805_HV [mil] "0805 with 30mil clearance between pads"
  rect 50x63 smd: 1(-40,0) 2(40,0)
  silkscreen extent -74,-40 74,40, body extent -43,-29 43,29, height 57
1206 [mm] "1206 from SM-752 data"
  rect 1.3x1.85 smd: 1(-1.45,0) 2(1.45,0)
  silkscreen extent -2.4,-1.21 2.4,1.21, body extent -1.7,-0.9 1.7,0.9, height 1.35
1206_190 [mm] "1206_190"
  rect 1.1x1.6 smd: 1(-1.7,0) 2(1.7,0)
  silkscreen extent -0.9,-1 0.9,1, body extent -1.75,-0.95 1.75,0.95, height 1.9
1210 [mm] "1210 from SM-752 data"
  rect 1.3x2.7 smd: 1(-1.45,0) 2(1.45,0)
  silkscreen extent -2.32,-1.57 2.32,1.57, body extent -1.7,-1.35 1.7,1.35, height 1.35
6032-28 [mm] "Medium Density IPC based on Vishay Sprague 293D datasheet."
  rect 2.55x2.3 smd: 1(-2.375,0) 2(2.375,0)
  silkscreen extent -3.96,-1.75 3.2,1.83, body extent -3.15,-1.75 3.15,1.75, height 2.8
AssemblyNote [mil] "Assembly Note"
AssemblyNoteLabel [mil] "Assembly Note for PCB Labels"
Bumpon_SJ61A1 [mil] "3M Cylindrical Bumpon black"
  round 1 on Mech4: 0(0,0)
  silkscreen extent -156,-156 156,156, body extent -156,-156 156,156, height 201
CONN_1751248 [mil] "Phoenix Contact"
  round 70 hole 43.31: 1(-68.9,0) 2(68.9,0)
  silkscreen extent -148,-142 148,146, body extent -148,-142 148,146, height 335
D0008A_N [mm] "SOIC, 8-Leads, Body 4.9x3.9mm, Pitch 1.27mm, IPC Medium Density"
  oval 1.45x0.6 smd: 1(-2.725,1.905) 2(-2.725,0.635) 3(-2.725,-0.635) 4(-2.725,-1.905) 5(2.725,-1.905) 6(2.725,-0.635) 7(2.725,0.635) 8(2.725,1.905)
  silkscreen extent -3.3,-2.5 0.9,2.5, body extent -3,-2.45 3,2.45, height 1.63
DBV0005A_N [mm] "SOT23, 5-Leads, Body 2.9x1.6mm, Pitch 0.95mm, Lead Span 2.8mm, IPC Medium Density"
  rrect17% 1x0.6 smd: 1(-1.375,0.95) 2(-1.375,0) 3(-1.375,-0.95) 4(1.375,-0.95) 5(1.375,0.95)
  silkscreen extent -1.63,-1.55 0.38,1.55, body extent -1.42,-1.46 1.42,1.46, height 1.09
DBV0006A_N [mm] "SOT23, 6-Leads, Body 2.9x1.6mm, Pitch 0.95mm, Lead Span 2.8mm, IPC Medium Density"
  rrect17% 1x0.6 smd: 1(-1.375,0.95) 2(-1.375,0) 3(-1.375,-0.95) 4(1.375,-0.95) 5(1.375,0) 6(1.375,0.95)
  silkscreen extent -1.68,-1.55 0.5,1.55, body extent -1.42,-1.46 1.42,1.46, height 1.12
DBZ0003A_N [mm] "SOT23, 3-Leads, Body 2.9x1.3mm, Pitch 0.95mm, Lead Span 2.4mm, IPC Medium Density"
  rrect17% 1x0.6 smd: 1(-1.2,0.95) 2(-1.2,-0.95) 3(1.2,0)
  silkscreen extent -1.65,-1.5 0.7,1.5, body extent -1.26,-1.46 1.26,1.46, height 0.98
DCK0005A_N [mm] "SOT353, 5-Leads, Body 2x1.3mm, Pitch 0.65mm, Lead Span 2.1mm, IPC Medium Density"
  rrect25% 0.85x0.4 smd: 1(-1.125,0.65) 2(-1.125,0) 3(-1.125,-0.65) 4(1.125,-0.65) 5(1.125,0.65)
  silkscreen extent -0.15,-1.1 0.15,1.1, body extent -1.14,-1 1.14,1, height 0.95
DGK0008A_N [mm] "TSOP, 8-Leads, Body 3x3mm, Pitch 0.65mm, IPC Medium Density"
  oval 1.35x0.45 smd: 1(-2.225,0.975) 2(-2.225,0.325) 3(-2.225,-0.325) 4(-2.225,-0.975) 5(2.225,-0.975) 6(2.225,-0.325) 7(2.225,0.325) 8(2.225,0.975)
  silkscreen extent -2.75,-1.55 0.95,1.55, body extent -2.45,-1.5 2.45,1.5, height 0.96
DNT0012B [mm] "SON, 12-Leads, Body 4x4mm, Pitch 0.5mm"
  rrect40% 0.6x0.25 smd: 1(-1.9,1.25) 2(-1.9,0.75) 3(-1.9,0.25) 4(-1.9,-0.25) 5(-1.9,-0.75) 6(-1.9,-1.25) 7(1.9,-1.25) 8(1.9,-0.75) 9(1.9,-0.25) 10(1.9,0.25) 11(1.9,0.75) 12(1.9,1.25)
  rrect4% 2.6x3 smd paste-1.3: 13(0,0)
  silkscreen extent -2.2,-2.2 2.2,2.2, body extent -2.05,-2.05 2.05,2.05, height 0.81
DRV0006A [mm] "SON, 6-Leads, Body 2x2mm, Pitch 0.65mm, Thermal Pad 1.6x1mm, TI Recommended"
  rrect33% 0.45x0.3 smd: 1(-0.975,0.65) 2(-0.975,0) 3(-0.975,-0.65) 4(0.975,-0.65) 5(0.975,0) 6(0.975,0.65)
  rrect14% 1x0.7 on Top Paste: 7(0,0.45) 7(0,-0.45)
  rrect10% 1x1.6 smd paste-0.5: 7(0,0)
  silkscreen extent -1.05,-1.2 1.05,1.2, body extent -1.05,-1.05 1.05,1.05, height 0.81
DSC0010J [mm] "SON, 10-Leads, Body 3x3mm, Pitch 0.5mm, Thermal Pad 2.4x1.65mm, TI Recommended"
  rrect100% 0.6x0.24 smd: 1(-1.4,1) 2(-1.4,0.5) 3(-1.4,0) 4(-1.4,-0.5) 5(-1.4,-1) 6(1.4,-1) 7(1.4,-0.5) 8(1.4,0) 9(1.4,0.5) 10(1.4,1)
  rrect6% 1.65x2.4 smd paste-0.825: 11(0,0)
  silkscreen extent -1.7,-1.7 1.7,1.7, body extent -1.57,-1.57 1.57,1.57, height 0.81
DSS0012B [mm] "SON, 12-Leads, Body 2x3mm, Pitch 0.5mm, Thermal Pad 2.65x1.0mm, TI Recommended"
  rrect40% 0.5x0.25 smd: 1(-0.95,1.25) 2(-0.95,0.75) 3(-0.95,0.25) 4(-0.95,-0.25) 5(-0.95,-0.75) 6(-0.95,-1.25) 7(0.95,-1.25) 8(0.95,-0.75) 9(0.95,-0.25) 10(0.95,0.25) 11(0.95,0.75) 12(0.95,1.25)
  rrect11% 0.949x1.168 on Top Paste: 13(0,0.684) 13(0,-0.684)
  rrect11% 1x2.65 smd paste-0.5: 13(0,0)
  silkscreen extent -1.05,-1.7 1.05,1.7, body extent -1,-1.5 1,1.5, height 0.81
EDJ0004A [mm] "Module, 4-Leads, Body 19.56x7.62mm"
  rect 1.75x1.75 hole 1.25: 1(-7.62,0)
  round 1.75 hole 1.25: 2(-5.08,0) 5(2.54,0) 7(7.62,0)
  silkscreen extent -9.78,-6.35 9.78,2.54, body extent -9.78,-6.35 9.78,1.27, height 10.15
EDJ0005A [mm] "Module, 5-Leads, Body 19.56x7.62mm"
  rect 1.75x1.75 hole 1.25: 1(-7.62,0)
  round 1.75 hole 1.25: 2(-5.08,0) 5(2.54,0) 6(5.08,0) 7(7.62,0)
  silkscreen extent -9.78,-6.35 9.78,2.54, body extent -9.78,-6.35 9.78,1.27, height 10.15
ESD_Overlay_Medium [mil]
  silkscreen extent -127,-109 125,110
FCC_disclaimer_stacked [mil]
Fiducial10-30 [mm]
  round 1 smd mask+1: 1(0,0)
  Top Layer keep-out circle w1.678: c0,0 r0.75
Keystone5000 [mil] "For Keystone 500x miniature loop terminals"
  round 80 hole 40: 1(0,0)
  silkscreen extent -52,-52 52,52, body extent -49,-49 49,49, height 182
Keystone5001 [mil] "For Keystone 500x miniature loop terminals"
  round 80 hole 40: 1(0,0)
  silkscreen extent -52,-52 52,52, body extent -49,-49 49,49, height 182
Keystone5002 [mil] "For Keystone 500x miniature loop terminals"
  round 80 hole 40: 1(0,0)
  silkscreen extent -52,-52 52,52, body extent -49,-49 49,49, height 182
LED_LTST-C190_G [mm] "Lite-On"
  rect 0.8x0.8 smd: 1(-0.75,0) 2(0.75,0)
  silkscreen extent 1.37,-0.5 1.75,0.5, body extent -0.85,-0.45 0.85,0.45, height 0.9
LED_LTST-C190_Red [mm] "Lite-On"
  rect 0.8x0.8 smd: 1(-0.75,0) 2(0.75,0)
  silkscreen extent -1.1,-0.8 1.8,0.8, body extent -0.85,-0.45 0.85,0.45, height 0.9
LP0003A_straight [mm] "TH, 3-Leads, Pin Spacing 1.27mm"
  rrect9% 1.5x1.07 hole 0.85: 1(0,1.27)
  rrect100% 1.5x1.07 hole 0.85: 2(0,0) 3(0,-1.27)
  silkscreen extent -1.33,-2.41 2.65,2.42, body extent -1.34,-2.41 2.35,2.41, height 6.84
MF03A_N [mm] "SOT23, 3-Leads, Body 2.9x1.3mm, Pitch 0.95mm, Lead Span 2.4mm, IPC Medium Density"
  rect 1.3x0.6 smd: 1(-1.05,0.95) 2(-1.05,-0.95) 3(1.05,0)
  silkscreen extent -1.18,-1.5 0.7,1.92, body extent -0.7,-1.5 0.7,1.5, height 1.12
Pb-Free_Overlay_Small [mil]
  silkscreen extent -46,-46 46,46
PogoPad [mil] "No Solder Paste"
  round 70 smd paste-35: 1(0,0)
POLYSWITCH_RXE135 [mil]
  round 85 hole 47: 1(-100,0) 2(100,0)
  silkscreen extent -335,-75 335,75
RGE0024B [mm] "QFN, 24-Leads, Body 4x4mm, Pitch 0.5mm, Thermal Pad 2.45x2.45mm, TI Recommended"
  oval 0.6x0.24 smd: 1(-1.9,1.25) 2(-1.9,0.75) 3(-1.9,0.25) 4(-1.9,-0.25) 5(-1.9,-0.75) 6(-1.9,-1.25) 13(1.9,-1.25) 14(1.9,-0.75) 15(1.9,-0.25) 16(1.9,0.25) 17(1.9,0.75) 18(1.9,1.25)
  oval 0.24x0.6 smd: 7(-1.25,-1.9) 8(-0.75,-1.9) 9(-0.25,-1.9) 10(0.25,-1.9) 11(0.75,-1.9) 12(1.25,-1.9) 19(1.25,1.9) 20(0.75,1.9) 21(0.25,1.9) 22(-0.25,1.9) 23(-0.75,1.9) 24(-1.25,1.9)
  rect 2.45x2.45 smd paste-1.225: 25(0,0)
  silkscreen extent -2.23,-2.22 2.22,2.23, body extent -2.07,-2.07 2.07,2.07, height 1.01
SOD-123 [mm] "On Semi recommended land pattern"
  rect 0.915x1.22 smd: 1(-1.637,0) 2(1.637,0)
  silkscreen extent -2.74,-1.17 2.03,1.17, body extent -1.93,-0.9 1.93,0.9, height 1.35
SOD-123FL [mm] "Copied from SOD-123"
  rect 0.915x1.22 smd: 1(-1.637,0) 2(1.637,0)
  silkscreen extent -2.74,-1.16 1.68,1.16, body extent -1.9,-0.9 1.9,0.9, height 1
Sullins_PBC02SAAN [mm] "Sullins 100mil, 1x2, 230 mil above insulator"
  rect 1.65x1.65 hole 1.016: 1(0,1.27)
  round 1.65 hole 1.016: 2(0,-1.27)
  silkscreen extent -1.37,-2.54 1.27,3.1, body extent -1.27,-2.54 1.27,2.54, height 8.38
WE-TDC_8018 [mm] "SMD, 4-Leads, Body 8x8mm"
  rect 3.6x1.4 smd: 1(0,3.8) 3(0,-3.8)
  rect 1.4x3.6 smd: 2(-3.8,0) 4(3.8,0)
  silkscreen extent -3.4,-3.4 3.4,3.55, body extent -4,-4 4,4, height 1.79
WE_LQS_252012 [mm] "SMD, 2-Leads, Body 2.5x2mm, Pitch 1.9mm"
  rect 1.1x2 smd: 1(-0.95,0) 2(0.95,0)
  silkscreen extent -0.1,-1 0.1,1, body extent -1.25,-1 1.25,1, height 1.2
WEEE_Minimum [mil] "WEEElie bin"
  silkscreen extent -95,-172 99,104
Wurth_750315371 [mm] "SMD, Body 12.6x8.3mm, Pitch 2.54mm"
  rect 1.83x1.09 smd: 1(-5.62,2.54) 2(-5.62,0) 3(-5.62,-2.54) 4(5.62,-2.54) 5(5.62,0) 6(5.62,2.54)
  silkscreen extent -6.3,-4.15 6.3,4.4, body extent -6.35,-4.2 6.35,4.2, height 4.11

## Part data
C1: library part 202R18W102KV4E, "CAP, CERM, 1000 pF, 2000 V, +/- 10%, X7R, 1206_190", Cap_Case=1206, Manufacturer=AVX, Supplier Part Number 1=478-4600-1-ND, TempCo=X7R, Tolerance_%=10, Value1=Unknown, Value2=2000V, ValueDisplayed=1000pF
C2: library part C0603C103J5RACTU, "CAP, CERM, 0.01 µF, 50 V, +/- 5%, X7R, 0603", Cap_Case=0603, Manufacturer="TDK Corporation", Supplier Part Number 1=445-5662-1-ND, TempCo=X7R, Tolerance_%=5, Value1=Unknown, Value2=50V, ValueDisplayed=0.01µF
C3 C4: "CAP, CERM, 2.2 µF, 50 V,+/- 10%, X7R, 1206", Cap_Case=1206, Manufacturer="Taiyo Yuden", Supplier Part Number 1=587-2911-1-ND, TempCo=X7R, Tolerance_%=10, Value2=50V, ValueDisplayed=2.2µF
C5 C8 C15 C19 C23 C28 C29 C84: library part C1608X7R1H104K, "CAP, CERM, 0.12µF ±10% 50V Ceramic Capacitor X7R 0603", Cap_Case=0603, Manufacturer=KEMET, Supplier Part Number 1=399-13273-1-ND, TempCo=X7R, Tolerance_%=10, Value1="0.017 ohm", Value2=50V, ValueDisplayed=0.1µF
C6: "CAP, CERM, 0.22 µF, 16 V, +/- 10%, X7R, 0603", Cap_Case=0603, Manufacturer="Wurth Elektronik", Supplier Part Number 1=732-7967-1-ND, TempCo=X7R, Tolerance_%=10, Value1=Unknown, Value2=16V, ValueDisplayed=0.22µF
C7 C22: "CAP, CERM, 10 µF, 25 V,+/- 10%, X7S, 0805", Cap_Case=0805, Manufacturer=MuRata, Supplier Part Number 1=490-10496-1-ND, TempCo=X7S, Tolerance_%=10, Value2=25V, ValueDisplayed=10µF
C9 C32 C43: library part GMK325AB7106MM-T, "CAP, CERM, 10µF ±10% 35V Ceramic Capacitor X7R 1210", Cap_Case=1210, Manufacturer="Taiyo Yuden", PartNumber=GMJ325KB7106KMHP, Supplier Part Number 1=587-4890-1-ND, TempCo=X7R, Tolerance_%=20, Value1=Unknown, Value2=35V, ValueDisplayed=10µF
C10: "CAP, CERM, 1000 pF, 16 V, +/- 10%, X7R, 0603", Cap_Case=0603, Manufacturer="Wurth Elektronik", Supplier Part Number 1=732-7953-1-ND, TempCo=X7R, Tolerance_%=10, Value1=Unknown, Value2=16V, ValueDisplayed=1000pF
C11 C18 C27 C33 C35 C38 C44: library part GRM188R71E105KA12D, "CAP, CERM, 1 µF, 25 V, +/- 10%, X7R, 0603", Cap_Case=0603, Manufacturer="TDK Corporation", Supplier Part Number 1=445-6931-1-ND, TempCo=X7R, Tolerance_%=10, Value1=Unknown, Value2=25V, ValueDisplayed=1µF
C12: library part GRM188R71H223KA01D, "CAP, CERM, 0.022 µF, 50 V, +/- 10%, X7R, 0603", Cap_Case=0603, Manufacturer="TDK Corporation", Supplier Part Number 1=445-1312-1-ND, TempCo=X7R, Tolerance_%=10, Value1=Unknown, Value2=50V, ValueDisplayed=0.022µF
C13: "CAP, CERM, 2.2 µF, 10 V,+/- 10%, X7R, 0603", Cap_Case=0603, Manufacturer=TDK, Supplier Part Number 1=445-5958-1-ND, TempCo=X7R, Tolerance_%=10, Value1="0.004058 ohm", Value2=10V, ValueDisplayed=2.2µF
C14: library part C0603C101J5GACTU, "CAP, CERM, 100 pF, 50 V, +/- 5%, C0G/NP0, 0603", Cap_Case=0603, Manufacturer=Murata, Supplier Part Number 1=490-4767-1-ND, TempCo=C0G/NP0, Tolerance_%=5, Value1=Unknown, Value2=50V, ValueDisplayed=100pF
C16 C17 C25 C26: "CAP, CERM, 10 µF, 25 V, +/- 10%, X7S, 0805", Cap_Case=0805, Manufacturer=MuRata, Supplier Part Number 1=490-10496-1-ND, TempCo=X7S, Tolerance_%=10, Value1=Unknown, Value2=25V, ValueDisplayed=10µF
C20: "CAP, CERM, 6.8 pF, 50 V, +/- 4%, C0G/NP0, 0603", Cap_Case=0603, Manufacturer=AVX, Supplier Part Number 1=478-1161-1-ND, TempCo=C0G/NP0, Tolerance_%=4, Value1="0.505 ohm", Value2=50V, ValueDisplayed=6.8pF
C21: "CAP, CERM, 0.22 µF, 16 V, +/- 10%, X7R, 0603", Cap_Case=0603, Manufacturer=MuRata, Supplier Part Number 1=490-3293-1-ND, TempCo=X7R, Tolerance_%=10, Value1=Unknown, Value2=16V, ValueDisplayed=0.22µF
C24: library part 06035A5R6CAT2A, "CAP, CERM, 5.6 pF, 50 V, +/- 5%, C0G/NP0, 0603", Cap_Case=0603, Manufacturer=Murata, Supplier Part Number 1=490-11472-1-ND, TempCo=C0G/NP0, Tolerance_%=5, Value1="0.568 ohm", Value2=50V, ValueDisplayed=5.6pF
C30: "CAP, CERM, 4700 pF, 50 V, +/- 10%, X7R, 0603", Cap_Case=0603, Manufacturer="Wurth Elektronik", Supplier Part Number 1=732-8005-1-ND, TempCo=X7R, Tolerance_%=10, Value1=Unknown, Value2=50V, ValueDisplayed=4700pF
C31: "CAP, CERM, 0.01 µF, 16 V, +/- 10%, X7R, 0603", Cap_Case=0603, Manufacturer="Wurth Elektronik", Supplier Part Number 1=732-7959-1-ND, TempCo=X7R, Tolerance_%=10, Value1=Unknown, Value2=16V, ValueDisplayed=0.01µF
C34 C37 C39 C41: "CAP, CERM, 2.2uF, 10V, +/-10%, X7R, 0805", Cap_Case=0805, Manufacturer=Kemet, Supplier Part Number 1=399-3522-1-ND, TempCo=X7R, Tolerance_%=10, Value1="0.008 ohm", Value2=10V, ValueDisplayed=2.2µF
C36 C40 C42: "CAP, CERM, 0.01 µF, 16 V,+/- 10%, X7R, 0603", Cap_Case=0603, Manufacturer="Wurth Elektronik", Supplier Part Number 1=732-7959-1-ND, TempCo=X7R, Tolerance_%=10, Value2=16V, ValueDisplayed=0.01µF
C45: library part C3216X7R1E475M, "CAP, CERM, 4.7 µF, 25 V, +/- 20%, X7R, 1206", Cap_Case=1206, Manufacturer=TDK, Supplier Part Number 1=445-1424-1-ND, TempCo=X7R, Tolerance_%=20, Value1="0.0063 ohm", Value2=25V, ValueDisplayed=4.7µF
C46 C47 C49 C54 C56 C57 C58 C61 C99 C100 C110 C111 C113 C116 C117 C135 C136 C137 C138 C139: "CAP, CERM, 0.1 µF, 25 V,+/- 10%, X5R, 0603", Cap_Case=0603, Manufacturer=AVX, Supplier Part Number 1=478-1244-1-ND, TempCo=X5R, Tolerance_%=10, Value1="0.048 ohm", Value2=25V, ValueDisplayed=0.1µF
C48 C53: library part C0805C105K8RACTU, "CAP, CERM, 1uF, 10V, +/-10%, X7R, 0805", Cap_Case=0805, Manufacturer="Samsung Electro-Mechanics", Supplier Part Number 1=1276-1275-1-ND, TempCo=X7R, Tolerance_%=10, Value1="0.015 ohm", Value2=10V, ValueDisplayed=1µF
C50 C51 C52: library part GRM21BR71H105KA12L, "CAP, CERM, 1 µF, 50 V, +/- 10%, X7R, 0805", Cap_Case=0805, Manufacturer=MuRata, Supplier Part Number 1=445-8890-1-ND, TempCo=X7R, Tolerance_%=10, Value1=Unknown, Value2=50V, ValueDisplayed=1µF
C55: "CAP, CERM, 10uF, 16V, +/-20%, X5R, 0603", Cap_Case=0603, Manufacturer="Taiyo Yuden", Supplier Part Number 1=587-3238-1-ND, TempCo=X5R, Tolerance_%=20, Value1=Unknown, Value2=16V, ValueDisplayed=10µF
C59: library part CL10B105KQ8NNNC, "CAP, CERM, 1 µF, 6.3 V, +/- 10%, X7R, 0603", Cap_Case=0603, Manufacturer="TDK Corporation", Supplier Part Number 1=445-13246-1-ND, TempCo=X7R, Tolerance_%=10, Value1=Unknown, Value2=6.3V, ValueDisplayed=1µF
C60 C62 C121: library part GRM21BR61E106KA73L, "CAP, CERM, 10 µF, 25 V, +/- 10%, X5R, 0805", Cap_Case=0805, Manufacturer="TDK Corporation", Supplier Part Number 1=445-14387-1-ND, TempCo=X5R, Tolerance_%=10, Value1=Unknown, Value2=25V, ValueDisplayed=10µF
C108 C109 C112 C114 C115: "CAP, TA, 10 µF, 25 V, +/- 10%, 0.45 ohm, SMD", Cap_Case=C, Manufacturer=Vishay-Sprague, Supplier Part Number 1=718-1098-1-ND, Tolerance_%=10, Value1="0.45 ohm", Value2=25V, ValueDisplayed=10µF
C120 C122: "CAP, CERM, 1000 pF, 50 V,+/- 5%, C0G/NP0, AEC-Q200 Grade 1, 0402", Cap_Case=0402, Manufacturer=TDK, Supplier Part Number 1=445-6885-1-ND, TempCo=C0G/NP0, Tolerance_%=5, Value2=50V, ValueDisplayed=1000pF
D1 D6 D10 D11: "LED, Green, SMD", Color=green, Manufacturer=Lite-On, Supplier Part Number 1=160-1435-1-ND, Value1=W, Value2=2V
D2 D7 D8: "Diode, Schottky, 45 V, 2 A, AEC-Q101, SOD-123FL", Manufacturer="ON Semiconductor", Supplier Part Number 1=NTS245SFT1GOSCT-ND, Value1=2A, Value2=0.63V
D3 D9: "Diode, Schottky, 40 V, 1 A, SOD-123", Manufacturer="Diodes Inc.", Supplier Part Number 1=1N5819HW-FDICT-ND, Value1=1A, Value2=0.45V
D5: "LED, Red, SMD", Color=red, Manufacturer=Lite-On, Power_TotalModule=0.0625, Supplier Part Number 1=160-1181-1-ND, Value1=0.0625W, Value2=2V
FID1 FID2 FID3: "Fiducial mark.  There is nothing to buy or mount.", Manufacturer=N/A
H1 H2 H3 H4 H5: "Bumpon, Cylindrical, 0.312 X 0.200, Black", Manufacturer=3M, Supplier Part Number 1=SJ5746-0-ND
J1 J4 J6: "Conn Term Block, 2POS, 3.5mm, TH", Manufacturer="Phoenix Contact", Supplier Part Number 1=277-5719-ND
J2 J5 J8 J12 J15: "Header, 100mil, 2x1, Gold, TH", Color=Black, Current_A=3, Manufacturer="Sullins Connector Solutions", Supplier Part Number 1=S1011E-02-ND, Voltage_V=1800
L1 L2: library part LQM18PN2R2MFH, "Inductor, Ferrite, 2.2 µH, 0.35 A, 0.38 ohm, SMD", Manufacturer=MuRata, Supplier Part Number 1=490-9571-1-ND, Value1="0.38 ohm", Value2=0.35A, ValueDisplayed=2.2µH
L3: "Ferrite Bead, 600 ohm @ 100 MHz, 1.3 A, 0603", Manufacturer=MuRata, Supplier Part Number 1=490-5258-1-ND, Value1="0.15 ohm", Value2=1.3A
